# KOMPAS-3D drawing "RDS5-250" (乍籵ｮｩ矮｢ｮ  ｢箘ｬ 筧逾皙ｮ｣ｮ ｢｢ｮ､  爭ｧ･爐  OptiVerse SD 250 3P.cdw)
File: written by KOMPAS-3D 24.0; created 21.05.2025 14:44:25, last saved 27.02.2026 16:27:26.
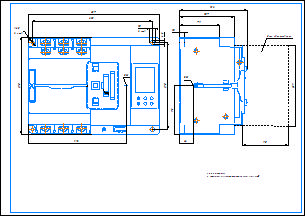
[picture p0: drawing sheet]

Document properties: Утвердил: Строгонов; Автор: keaz-admin; Проверил: Дорошев; Форматы листов документа: A2; Полное имя файла: D:\Проекты\OptiVerse SD\OptiVerse SD\OptiVerse SD 250 3P\КД\ГЖИК.648456.001ГЧ Устройство автоматического ввода резерва OptiVerse SD 250 3P (без рамки).cdw; Масса: 6.7; Т. контр.: Пашков А.Е.; Наименование: Устройство автоматического ввода резерва OptiVerse SD 250 3P / Габаритный чертеж; Н. контр.: Гаврикова; Количество листов документа: 1; Разработал: Сулейманова

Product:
- Body: Тело 3
    Масса: 0.00002
- Body: Тело 4
    Масса: 0.000006
- Component [assembly]: RDS5-250.STEP  | qty 1  | Масса: 29.402335; source file: ..\3D\Сборка OptiVerse SD 250 3P.a3d
- Part/product: RDS5-250
    Масса: 29.402357
    Форматы листов документа: A2

Views: Вид 1
Referenced files in D:\Проекты\OptiVerse SD\OptiVerse SD\OptiVerse SD 250 3P\КД\: ГЖИК.648456.001СБ Устройство автоматического ввода резерва OptiVerse SD 250 3P.cdw
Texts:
  Устройство автоматического
  ввода резерва OptiVerse SD 250 3P
  Габаритный чертеж
  ГЖИК.648456.001ГЧ
  Сулейманова
  Дорошев
  ГЖИК.648456.001
  Гаврикова
  Строгонов
  АО "КЭАЗ"
  Пашков А.Е.
  Без основной надписи.
Dimensions and other numbers on the sheet: 190; 132; 107; 10; 79; 257; 235; 170; 6,5; 2 отв.; 192; 1:1; 0; 1; 2; 6,7

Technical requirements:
  Ц.М. - центр масс.
  Отклонение координат от центра масс не более 10 %.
